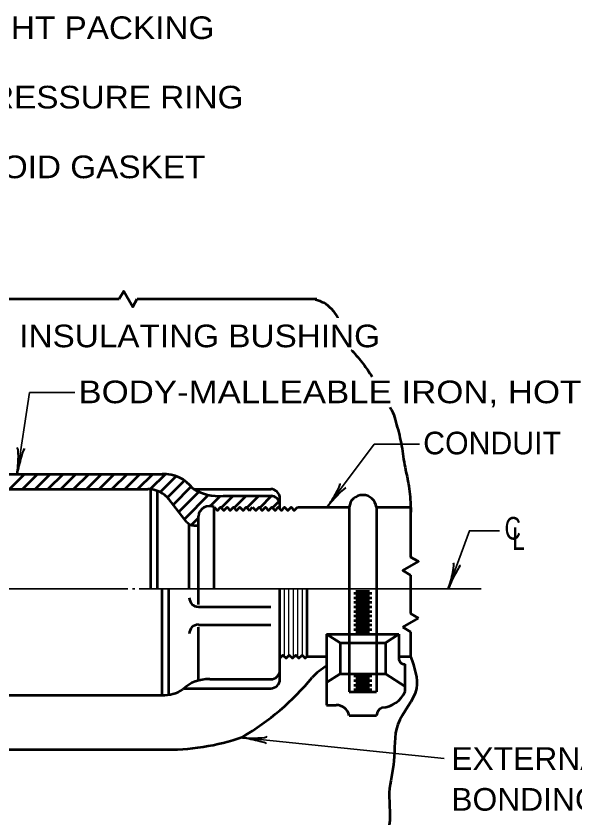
# Model space of a CAD drawing. Extents: x -50 to 806, y -9 to 535.
# Drawn here: x 316.3 to 390.3, y 361.3 to 467.5 of the extents above; entities that cross this region are included whole.
import ezdxf

# ---------------------------------------------------------------- set-up
doc = ezdxf.new("R2010")
doc.units = 0
doc.header["$LTSCALE"] = 1.2
doc.layers.add('1', color=7, linetype='Continuous', lineweight=35)

msp = doc.modelspace()

# ---------------------------------------------------------------- linework, layer by layer
at = {"layer": '1', "lineweight": 53}
for p, q in [((290.321, 430.051), (329.921, 430.051)), ((332.321, 430.051), (356.141, 430.051)), ((304.427, 406.854), (335.627, 406.854)), ((317.396, 406.854), (315.393, 404.851)), ((319.093, 406.854), (317.09, 404.851)), ((320.79, 406.854), (318.787, 404.851)), ((322.487, 406.854), (320.484, 404.851)), ((324.184, 406.854), (322.181, 404.851)), ((325.881, 406.854), (323.878, 404.851)), ((327.579, 406.854), (325.575, 404.851)), ((329.276, 406.854), (327.272, 404.851)), ((330.973, 406.854), (328.969, 404.851)), ((332.67, 406.854), (330.667, 404.851)), ((334.367, 406.854), (332.363, 404.851)), ((336.058, 406.849), (334.045, 404.836)), ((337.466, 406.559), (335.36, 404.453)), ((338.583, 405.98), (336.341, 403.737)), ((339.479, 405.179), (337.085, 402.785)), ((278.321, 404.851), (333.715, 404.851)), ((334.121, 391.651), (334.121, 404.828)), ((335.021, 391.651), (335.021, 404.606)), ((340.491, 404.494), (337.83, 401.832)), ((341.767, 404.072), (338.574, 400.879)), ((339.814, 404.849), (350.021, 404.849)), ((343.317, 403.925), (341.995, 402.603)), ((345.038, 403.949), (343.455, 402.366)), ((343.722, 403.949), (350.021, 403.949)), ((346.735, 403.949), (345.152, 402.366)), ((348.432, 403.949), (346.849, 402.366)), ((350.129, 403.949), (348.546, 402.366)), ((338.861, 400.512), (336.552, 403.467)), ((351.116, 403.239), (350.243, 402.366)), ((351.221, 402.237), (351.221, 403.649)), ((342.521, 391.651), (342.521, 402.451)), ((347.188, 402.027), (347.613, 402.451)), ((353.553, 402.451), (360.411, 402.451)), ((360.411, 402.451), (360.411, 377.99)), ((364.012, 402.451), (364.012, 377.99)), ((364.012, 402.451), (368.553, 402.451)), ((368.553, 402.451), (368.553, 395.851)), ((340.421, 401.029), (339.443, 400.051)), ((340.421, 389.551), (340.421, 401.251)), ((339.221, 391.651), (339.221, 400.203)), ((339.806, 400.051), (340.421, 400.051)), ((368.553, 393.451), (368.553, 388.351)), ((335.621, 377.551), (335.621, 391.651)), ((336.521, 377.593), (336.521, 391.651)), ((351.221, 379.651), (351.221, 391.651)), ((354.821, 382.651), (354.821, 391.651)), ((361.012, 391.051), (363.411, 391.051)), ((361.312, 391.351), (363.112, 391.351)), ((361.012, 390.451), (363.411, 390.451)), ((361.312, 390.751), (363.112, 390.751)), ((361.312, 390.151), (363.112, 390.151)), ((340.421, 389.251), (350.021, 389.251)), ((361.012, 389.851), (363.411, 389.851)), ((361.012, 389.251), (363.411, 389.251)), ((361.312, 389.551), (363.112, 389.551)), ((361.312, 388.951), (363.112, 388.951)), ((361.012, 388.651), (363.411, 388.651)), ((361.012, 388.051), (363.411, 388.051)), ((361.312, 388.351), (363.112, 388.351)), ((369.592, 387.751), (368.553, 388.351)), ((340.421, 386.851), (350.021, 386.851)), ((361.012, 387.451), (363.411, 387.451)), ((361.012, 386.851), (363.411, 386.851)), ((361.312, 387.751), (363.112, 387.751)), ((361.312, 387.151), (363.112, 387.151)), ((367.514, 386.551), (369.592, 387.751)), ((340.421, 379.489), (340.421, 386.551)), ((361.012, 386.251), (363.411, 386.251)), ((361.312, 386.551), (363.112, 386.551)), ((361.312, 385.951), (363.112, 385.951)), ((368.553, 385.951), (367.514, 386.551)), ((368.553, 385.951), (368.553, 382.651)), ((357.411, 385.651), (367.012, 385.651)), ((357.411, 385.651), (357.411, 376.236)), ((359.212, 384.482), (357.411, 385.651)), ((365.212, 384.482), (367.012, 385.651)), ((367.012, 385.651), (367.012, 382.651)), ((359.212, 384.482), (359.212, 380.39)), ((359.212, 384.482), (365.212, 384.482)), ((365.212, 384.482), (365.212, 380.39)), ((354.821, 382.651), (357.411, 382.651)), ((367.012, 382.651), (368.553, 382.651)), ((367.839, 378.045), (367.839, 381.644)), ((341.921, 379.651), (350.021, 379.651)), ((359.212, 380.39), (357.411, 379.221)), ((359.212, 380.39), (365.212, 380.39)), ((361.012, 380.09), (363.411, 380.09)), ((361.012, 379.49), (363.411, 379.49)), ((361.312, 379.79), (363.112, 379.79)), ((365.212, 380.39), (367.839, 378.684)), ((338.512, 378.451), (350.021, 378.451)), ((361.012, 378.89), (363.411, 378.89)), ((361.012, 378.29), (363.411, 378.29)), ((361.312, 379.19), (363.112, 379.19)), ((361.312, 378.59), (363.112, 378.59)), ((293.021, 377.551), (335.621, 377.551)), ((360.411, 377.99), (364.012, 377.99)), ((357.411, 376.236), (358.684, 376.236)), ((360.411, 374.866), (364.012, 374.866)), ((273.521, 370.351), (335.621, 370.351))]:
    msp.add_line(p, q, dxfattribs=at)
at = {"layer": '1'}
for p, q in [((316.395, 406.89), (318.035, 417.658)), ((318.035, 417.658), (324.035, 417.658)), ((297.039, 391.651), (331.078, 391.651)), ((331.678, 391.651), (331.978, 391.651)), ((332.578, 391.651), (362.321, 391.651)), ((362.321, 391.651), (364.421, 391.651)), ((364.421, 391.651), (377.887, 391.651)), ((346.044, 371.93), (373.008, 369.171))]:
    msp.add_line(p, q, dxfattribs=at)
at = {"layer": '1', "lineweight": 25}
for p, q in [((351.821, 382.66), (351.821, 391.651)), ((352.421, 382.813), (352.421, 391.651)), ((353.021, 382.564), (353.021, 391.651)), ((353.621, 382.558), (353.621, 391.651)), ((354.221, 382.806), (354.221, 391.651))]:
    msp.add_line(p, q, dxfattribs=at)
at = {"layer": '1', "lineweight": 53}
for points in [[(329.921, 430.051), (330.521, 431.09), (331.721, 429.012), (332.321, 430.051)], [(342.521, 402.451), (342.945, 402.027), (343.37, 402.451), (343.794, 402.027), (344.218, 402.451), (344.643, 402.027), (345.067, 402.451), (345.491, 402.027), (345.916, 402.451), (346.34, 402.027), (346.764, 402.451), (347.188, 402.027)], [(347.613, 402.451), (348.037, 402.027), (348.461, 402.451), (348.886, 402.027), (349.31, 402.451), (349.734, 402.027), (350.159, 402.451), (350.583, 402.027), (351.007, 402.451), (351.431, 402.027), (351.856, 402.451), (352.28, 402.027), (352.704, 402.451), (353.129, 402.027), (353.553, 402.451)], [(368.553, 393.451), (367.514, 394.051), (369.592, 395.251), (368.553, 395.851)], [(351.221, 382.462), (351.62, 382.861), (352.045, 382.437), (352.469, 382.861), (352.893, 382.437), (353.318, 382.861), (353.742, 382.437), (354.166, 382.861), (354.591, 382.437), (354.805, 382.651)]]:
    msp.add_lwpolyline(points, dxfattribs=at)
at = {"layer": '1'}
for points in [[(357.529, 402.54), (363.731, 410.812), (369.731, 410.812)], [(373.544, 391.651), (376.356, 399.34), (380.324, 399.34)]]:
    msp.add_lwpolyline(points, dxfattribs=at)
at = {"layer": '1', "lineweight": 53}
for centre, radius, start, end in [((335.784, 401.948), 4.908, 37.40887, 91.82799), ((343.146, 410.384), 6.461, 237.57892, 275.11473), ((333.715, 401.251), 3.6, 37.99971, 90), ((350.021, 403.649), 1.2, 0, 90), ((350.021, 402.749), 1.2, 0, 90), ((362.212, 402.257), 1.81, 6.16262, 173.83738), ((341.865, 401.162), 1.446, 63.00162, 176.48814), ((339.806, 401.251), 1.2, 217.99816, 270), ((340.421, 390.451), 1.2, 180, 270), ((340.421, 385.693), 1.2, 90, 180), ((367.788, 382.446), 0.803, 165.23922, 273.58468), ((350.021, 380.851), 1.2, 270, 0), ((361.927, 373.829), 8.831, 120.75676, 136.54084), ((341.676, 374.907), 4.751, 87.03706, 134.14391), ((328.094, 402.627), 35.615, 300.74714, 320.35337), ((350.021, 379.651), 1.2, 270, 0), ((335.863, 381.993), 4.448, 266.87761, 304.24831), ((364.521, 379.535), 3.637, 273.86793, 335.80007), ((358.718, 374.505), 1.731, 12.01693, 91.12043), ((365.394, 374.657), 1.398, 116.66219, 171.42653), ((336.38, 400.533), 30.191, 268.56002, 289.18704)]:
    msp.add_arc(centre, radius, start, end, dxfattribs=at)
at = {"layer": '1', "lineweight": 40}
for centre, major_axis, ratio, start_param, end_param in [((316.264, 408.234), (-0.137, -2.147), 0.122415, 0.8963533, 3.1415927), ((316.264, 408.234), (-0.137, -2.147), 0.122415, 0.8963533, 3.1415927), ((316.848, 408.181), (-0.526, -2.052), 0.07063, 3.1407148, 5.41811), ((316.848, 408.181), (-0.526, -2.052), 0.07063, 3.1407148, 5.41811), ((358.049, 403.786), (-1.136, -1.827), 0.122415, 0.8963533, 3.1415927), ((358.049, 403.786), (-1.136, -1.827), 0.122415, 0.8963533, 3.1415927), ((358.539, 403.463), (1.433, 1.56), 0.07063, 6.2823074, 8.5597026), ((358.539, 403.463), (1.433, 1.56), 0.07063, 6.2823074, 8.5597026), ((373.682, 392.995), (-0.56, -2.077), 0.122415, 0.8963533, 3.1415927), ((374.244, 392.827), (-0.922, -1.907), 0.07063, 3.1407148, 5.41811), ((347.356, 371.541), (-2.075, 0.424), 0.07063, 3.1407148, 5.41811), ((347.38, 372.127), (-2.151, 0.032), 0.122415, 0.8963533, 3.1415927)]:
    msp.add_ellipse(centre, major_axis=major_axis, ratio=ratio, start_param=start_param, end_param=end_param, dxfattribs=at)
at = {"layer": '1', "lineweight": 53}
for points in [[(355.964, 429.985), (357.012, 429.565), (358.839, 427.623), (358.882, 427.546)], [(360.733, 423.279), (360.781, 423.224), (362.266, 421.453), (363.444, 419.724)], [(365.792, 415.723), (366.206, 414.997), (366.606, 413.74), (367.291, 410.941), (367.748, 408.085), (368.262, 405.571), (368.548, 402.772), (368.564, 401.785)], [(368.553, 382.651), (369.313, 378.447), (366.863, 373.666), (366.326, 368.825), (365.728, 364.642), (365.609, 359.741), (364.952, 358.127), (362.263, 353.645), (362.083, 353.242)]]:
    msp.add_spline(points, degree=3, dxfattribs=at)

# ---------------------------------------------------------------- texts
at = {"layer": '1'}
for s, width, p in [('WATERTIGHT PACKING', 1.1, (292.286, 464.493)), ('STEEL PRESSURE RING', 1.1, (294.655, 455.291)), ('VELLUMOID GASKET', 1.1, (296.712, 446.05)), ('INSULATING BUSHING', 1.1, (316.68, 423.648)), ('BODY-MALLEABLE IRON, HOT DIP GALV.', 1.15, (324.522, 416.232)), ('C', 0.75, (381.001, 398.166)), ('L', 0.75, (382.028, 396.796)), ('EXTERNAL', 1.05, (373.947, 367.643)), ('BONDING JUMPER', 1.05, (373.947, 362.243))]:
    msp.add_text(s, height=3, dxfattribs=dict(at, width=width)).set_placement(p)
msp.add_text('CONDUIT', height=3, dxfattribs=at).set_placement((370.218, 409.457))

doc.saveas('drawing.dxf')
